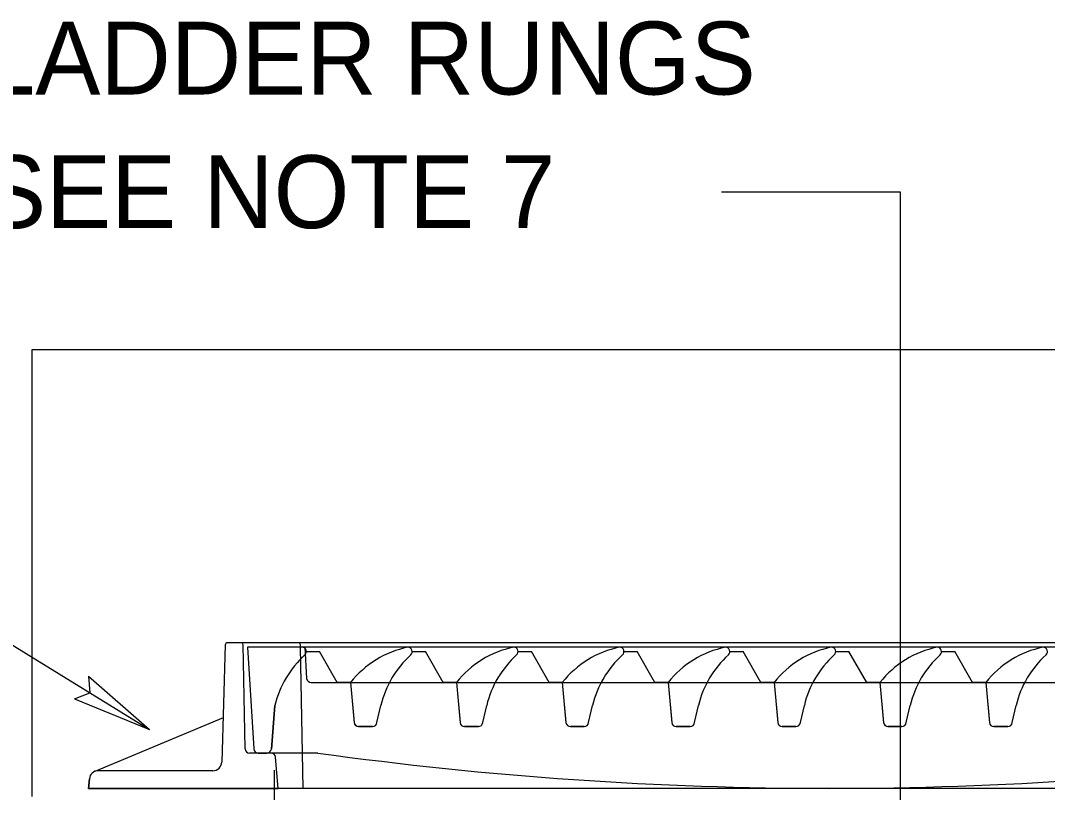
# Model space of a CAD drawing. Extents: x 9.6 to 16.8, y 2.2 to 12.2.
# Drawn here: x 11.1 to 11.945, y 8.579 to 9.215 of the extents above; entities that cross this region are included whole.
import ezdxf

# ---------------------------------------------------------------- set-up
doc = ezdxf.new("R2010")
doc.units = 0
for name, color, linetype in [('DETL-DIMS', 7, 'Continuous'), ('DETL-LINE', 7, 'Continuous'), ('DETL-NOTE', 7, 'Continuous')]:
    doc.layers.add(name, color=color, linetype=linetype)

msp = doc.modelspace()

# ---------------------------------------------------------------- linework, layer by layer
at = {"layer": 'DETL-DIMS'}
for p, q in [((11.67678, 9.07392), (11.82388, 9.07392)), ((11.82388, 9.07392), (11.82388, 8.28624)), ((10.59322, 9.00796), (11.20616, 8.63114)), ((11.15576, 8.67498), (11.20616, 8.63114)), ((11.15576, 8.67498), (11.15706, 8.66133)), ((11.14427, 8.65627), (11.15706, 8.66133)), ((11.14427, 8.65627), (11.20616, 8.63114))]:
    msp.add_line(p, q, dxfattribs=at)
at = {"layer": 'DETL-LINE'}
for p, q in [((11.10965, 8.57592), (11.10965, 8.94412)), ((11.10965, 8.94412), (13.41718, 8.94412)), ((11.26847, 8.70076), (11.26554, 8.60427)), ((11.26847, 8.70076), (11.26554, 8.60427)), ((12.26153, 8.70252), (11.27029, 8.70252)), ((11.28127, 8.70252), (11.27029, 8.70252)), ((11.28479, 8.61531), (11.28309, 8.70074)), ((11.28479, 8.61531), (11.28309, 8.70074)), ((11.33031, 8.69889), (11.33027, 8.70074)), ((11.33201, 8.61175), (11.33031, 8.69889)), ((11.33383, 8.69889), (11.33544, 8.67325)), ((11.33906, 8.66984), (12.14489, 8.66984)), ((11.37157, 8.66984), (11.37461, 8.63676)), ((11.45871, 8.66984), (11.46174, 8.63676)), ((11.54584, 8.66984), (11.54888, 8.63676)), ((11.63298, 8.66984), (11.63601, 8.63676)), ((11.72011, 8.66984), (11.72315, 8.63676)), ((11.80725, 8.66984), (11.81028, 8.63676)), ((11.89438, 8.66984), (11.89741, 8.63676)), ((11.30639, 8.61508), (11.30937, 8.65087)), ((11.39323, 8.63692), (11.39651, 8.65087)), ((11.48037, 8.63692), (11.48364, 8.65087)), ((11.5675, 8.63692), (11.57078, 8.65087)), ((11.65464, 8.63692), (11.65791, 8.65087)), ((11.74177, 8.63692), (11.74505, 8.65087)), ((11.82891, 8.63692), (11.83218, 8.65087)), ((11.91604, 8.63692), (11.91931, 8.65087)), ((11.2666, 8.6408), (11.16109, 8.59667)), ((11.37821, 8.63354), (11.38961, 8.63354)), ((11.46535, 8.63354), (11.47675, 8.63354)), ((11.55248, 8.63354), (11.56388, 8.63354)), ((11.63962, 8.63354), (11.65102, 8.63354)), ((11.72675, 8.63354), (11.73815, 8.63354)), ((11.81389, 8.63354), (11.82528, 8.63354)), ((11.90102, 8.63354), (11.91242, 8.63354)), ((11.30623, 8.61175), (11.28842, 8.61175)), ((11.2955, 8.61175), (11.30278, 8.61175)), ((11.31209, 8.58271), (11.30984, 8.60844)), ((11.33258, 8.58271), (11.33201, 8.61175)), ((11.25828, 8.59723), (11.16389, 8.59723)), ((11.25828, 8.59723), (11.16389, 8.59723)), ((11.30592, 7.0371), (11.30902, 8.5978)), ((11.15596, 8.58271), (11.15666, 8.5906)), ((12.26693, 8.58271), (11.15596, 8.58271))]:
    msp.add_line(p, q, dxfattribs=at)
for points in [[(11.33157, 8.69889), (11.28667, 8.69889), (11.29188, 8.61516)], [(11.15666, 8.5906), (11.15596, 8.58271), (11.31209, 8.58271), (11.30984, 8.60844)], [(11.30623, 8.61175), (11.30278, 8.61175), (11.2955, 8.61175), (11.28842, 8.61175)]]:
    msp.add_lwpolyline(points, dxfattribs=at)
for centre, radius, start, end in [((11.27029, 8.7007), 0.00182, 90, 178.21454), ((11.27029, 8.7007), 0.00182, 90, 178.21454), ((11.28127, 8.7007), 0.00182, 1.14576, 90), ((11.28127, 8.7007), 0.00182, 1.14576, 90), ((11.32845, 8.7007), 0.00182, 1.12223, 90), ((11.33157, 8.69526), 0.00363, 312.13904, 90), ((11.43513, 8.61948), 0.08109, 101.68474, 141.60267), ((11.4187, 8.69526), 0.00363, 312.13904, 90), ((11.52226, 8.61948), 0.08109, 101.68474, 141.60267), ((11.50584, 8.69526), 0.00363, 312.13904, 90), ((11.6094, 8.61948), 0.08109, 101.68474, 141.60267), ((11.59297, 8.69526), 0.00363, 312.13904, 90), ((11.69653, 8.61948), 0.08109, 101.68474, 141.60267), ((11.68011, 8.69526), 0.00363, 312.13904, 90), ((11.78367, 8.61948), 0.08109, 101.68474, 141.60267), ((11.76724, 8.69526), 0.00363, 312.13904, 90), ((11.8708, 8.61948), 0.08109, 101.68474, 141.60267), ((11.85438, 8.69526), 0.00363, 312.13904, 90), ((11.95794, 8.61948), 0.08109, 101.68474, 141.60267), ((11.94151, 8.69526), 0.00363, 312.13904, 90), ((11.38833, 8.63235), 0.0811, 132.0547, 166.79706), ((11.47547, 8.63235), 0.0811, 132.0547, 166.79706), ((11.5626, 8.63235), 0.0811, 132.0547, 166.79706), ((11.64973, 8.63235), 0.0811, 132.0547, 166.79706), ((11.73687, 8.63235), 0.0811, 132.0547, 166.79706), ((11.824, 8.63235), 0.0811, 132.0547, 166.79706), ((11.91114, 8.63235), 0.0811, 132.0547, 166.79706), ((11.99827, 8.63235), 0.0811, 132.0547, 166.79706), ((11.33906, 8.67347), 0.00363, 183.58744, 270.00072), ((11.37821, 8.63717), 0.00363, 186.50491, 270), ((11.38961, 8.63717), 0.00363, 270, 356.02653), ((11.46535, 8.63717), 0.00363, 186.50491, 270), ((11.47675, 8.63717), 0.00363, 270, 356.02653), ((11.55248, 8.63717), 0.00363, 186.50491, 270), ((11.56388, 8.63717), 0.00363, 270, 356.02653), ((11.63962, 8.63717), 0.00363, 186.50491, 270), ((11.65102, 8.63717), 0.00363, 270, 356.02653), ((11.72675, 8.63717), 0.00363, 186.50491, 270), ((11.73815, 8.63717), 0.00363, 270, 356.02653), ((11.81389, 8.63717), 0.00363, 186.50491, 270), ((11.82528, 8.63717), 0.00363, 270, 356.02653), ((11.90102, 8.63717), 0.00363, 186.50491, 270), ((11.91242, 8.63717), 0.00363, 270, 356.02653), ((11.28842, 8.61539), 0.00363, 181.14576, 270), ((11.28842, 8.61539), 0.00363, 181.14576, 270), ((11.2955, 8.61539), 0.00363, 183.5616, 270), ((11.30278, 8.61539), 0.00363, 270, 355.24411), ((11.25828, 8.60449), 0.00726, 270, 358.25842), ((11.25828, 8.60449), 0.00726, 270, 358.25842), ((11.30623, 8.60812), 0.00363, 5, 90), ((11.30623, 8.60812), 0.00363, 5, 90), ((11.16389, 8.58997), 0.00726, 90, 175), ((11.16389, 8.58997), 0.00726, 90, 175)]:
    msp.add_arc(centre, radius, start, end, dxfattribs=at)
at = {"layer": 'DETL-NOTE'}
for p, q in [((11.26853, 8.70252), (11.26853, 8.70252)), ((11.28302, 8.70252), (11.28302, 8.70252)), ((11.28305, 8.70252), (11.28305, 8.70252)), ((12.24515, 8.69889), (11.28667, 8.69889)), ((11.28667, 8.69889), (11.29188, 8.61516)), ((11.28667, 8.69889), (11.28667, 8.69889)), ((11.3352, 8.69526), (11.34609, 8.69526)), ((11.36068, 8.66984), (11.34609, 8.69526)), ((11.42233, 8.69526), (11.43323, 8.69526)), ((11.44782, 8.66984), (11.43323, 8.69526)), ((11.50947, 8.69526), (11.52036, 8.69526)), ((11.53495, 8.66984), (11.52036, 8.69526)), ((11.5966, 8.69526), (11.6075, 8.69526)), ((11.62208, 8.66984), (11.6075, 8.69526)), ((11.68374, 8.69526), (11.69463, 8.69526)), ((11.70922, 8.66984), (11.69463, 8.69526)), ((11.77087, 8.69526), (11.78177, 8.69526)), ((11.79635, 8.66984), (11.78177, 8.69526)), ((11.85801, 8.69526), (11.8689, 8.69526)), ((11.88349, 8.66984), (11.8689, 8.69526)), ((11.37157, 8.66984), (11.36068, 8.66984)), ((11.37157, 8.66984), (11.37459, 8.63692)), ((11.45871, 8.66984), (11.44782, 8.66984)), ((11.45871, 8.66984), (11.46173, 8.63692)), ((11.54584, 8.66984), (11.53495, 8.66984)), ((11.54584, 8.66984), (11.54886, 8.63692)), ((11.63298, 8.66984), (11.62208, 8.66984)), ((11.63298, 8.66984), (11.636, 8.63692)), ((11.72011, 8.66984), (11.70922, 8.66984)), ((11.72011, 8.66984), (11.72313, 8.63692)), ((11.80725, 8.66984), (11.79635, 8.66984)), ((11.80725, 8.66984), (11.81027, 8.63692)), ((11.89438, 8.66984), (11.88349, 8.66984)), ((11.89438, 8.66984), (11.8974, 8.63692)), ((11.30937, 8.65087), (11.30639, 8.61508)), ((11.39323, 8.63692), (11.39651, 8.65087)), ((11.48037, 8.63692), (11.48364, 8.65087)), ((11.5675, 8.63692), (11.57078, 8.65087)), ((11.65464, 8.63692), (11.65791, 8.65087)), ((11.74177, 8.63692), (11.74505, 8.65087)), ((11.82891, 8.63692), (11.83218, 8.65087)), ((11.91604, 8.63692), (11.91931, 8.65087)), ((11.38961, 8.63354), (11.37821, 8.63354)), ((11.47675, 8.63354), (11.46535, 8.63354)), ((11.56388, 8.63354), (11.55248, 8.63354)), ((11.65102, 8.63354), (11.63962, 8.63354)), ((11.73815, 8.63354), (11.72675, 8.63354)), ((11.82528, 8.63354), (11.81389, 8.63354)), ((11.91242, 8.63354), (11.90102, 8.63354)), ((11.30278, 8.61175), (11.2955, 8.61175)), ((11.34476, 8.61175), (11.30278, 8.61175)), ((11.15596, 8.58271), (11.15596, 8.58271)), ((11.31209, 8.58271), (11.31209, 8.58271))]:
    msp.add_line(p, q, dxfattribs=at)
for centre, radius, start, end in [((11.33157, 8.69526), 0.00363, 312.13904, 90), ((11.43513, 8.61948), 0.08109, 101.68474, 141.60267), ((11.4187, 8.69526), 0.00363, 312.13904, 90), ((11.52226, 8.61948), 0.08109, 101.68474, 141.60267), ((11.50584, 8.69526), 0.00363, 312.13904, 90), ((11.6094, 8.61948), 0.08109, 101.68474, 141.60267), ((11.59297, 8.69526), 0.00363, 312.13904, 90), ((11.69653, 8.61948), 0.08109, 101.68474, 141.60267), ((11.68011, 8.69526), 0.00363, 312.13904, 90), ((11.78367, 8.61948), 0.08109, 101.68474, 141.60267), ((11.76724, 8.69526), 0.00363, 312.13904, 90), ((11.8708, 8.61948), 0.08109, 101.68474, 141.60267), ((11.85438, 8.69526), 0.00363, 312.13904, 90), ((11.95794, 8.61948), 0.08109, 101.68474, 141.60267), ((11.94151, 8.69526), 0.00363, 312.13904, 90), ((11.38833, 8.63235), 0.0811, 132.0547, 166.79706), ((11.47547, 8.63235), 0.0811, 132.0547, 166.79706), ((11.5626, 8.63235), 0.0811, 132.0547, 166.79706), ((11.64973, 8.63235), 0.0811, 132.0547, 166.79706), ((11.73687, 8.63235), 0.0811, 132.0547, 166.79706), ((11.824, 8.63235), 0.0811, 132.0547, 166.79706), ((11.91114, 8.63235), 0.0811, 132.0547, 166.79706), ((11.99827, 8.63235), 0.0811, 132.0547, 166.79706), ((11.37821, 8.63717), 0.00363, 183.97347, 270), ((11.38961, 8.63717), 0.00363, 270, 356.02653), ((11.46535, 8.63717), 0.00363, 183.97347, 270), ((11.47675, 8.63717), 0.00363, 270, 356.02653), ((11.55248, 8.63717), 0.00363, 183.97347, 270), ((11.56388, 8.63717), 0.00363, 270, 356.02653), ((11.63962, 8.63717), 0.00363, 183.97347, 270), ((11.65102, 8.63717), 0.00363, 270, 356.02653), ((11.72675, 8.63717), 0.00363, 183.97347, 270), ((11.73815, 8.63717), 0.00363, 270, 356.02653), ((11.81389, 8.63717), 0.00363, 183.97347, 270), ((11.82528, 8.63717), 0.00363, 270, 356.02653), ((11.90102, 8.63717), 0.00363, 183.97347, 270), ((11.91242, 8.63717), 0.00363, 270, 356.02653), ((11.2955, 8.61539), 0.00363, 183.5616, 270), ((11.30278, 8.61539), 0.00363, 270, 355.24411), ((11.76591, 11.65058), 3.06787, 262.10963, 277.89037)]:
    msp.add_arc(centre, radius, start, end, dxfattribs=at)

# ---------------------------------------------------------------- texts
for s, p in [('LADDER RUNGS', (11.06753, 9.15392)), ('SEE NOTE 7', (11.06749, 9.04392))]:
    msp.add_text(s, height=0.06, rotation=359.99999, dxfattribs=at).set_placement(p)

doc.saveas('drawing.dxf')
